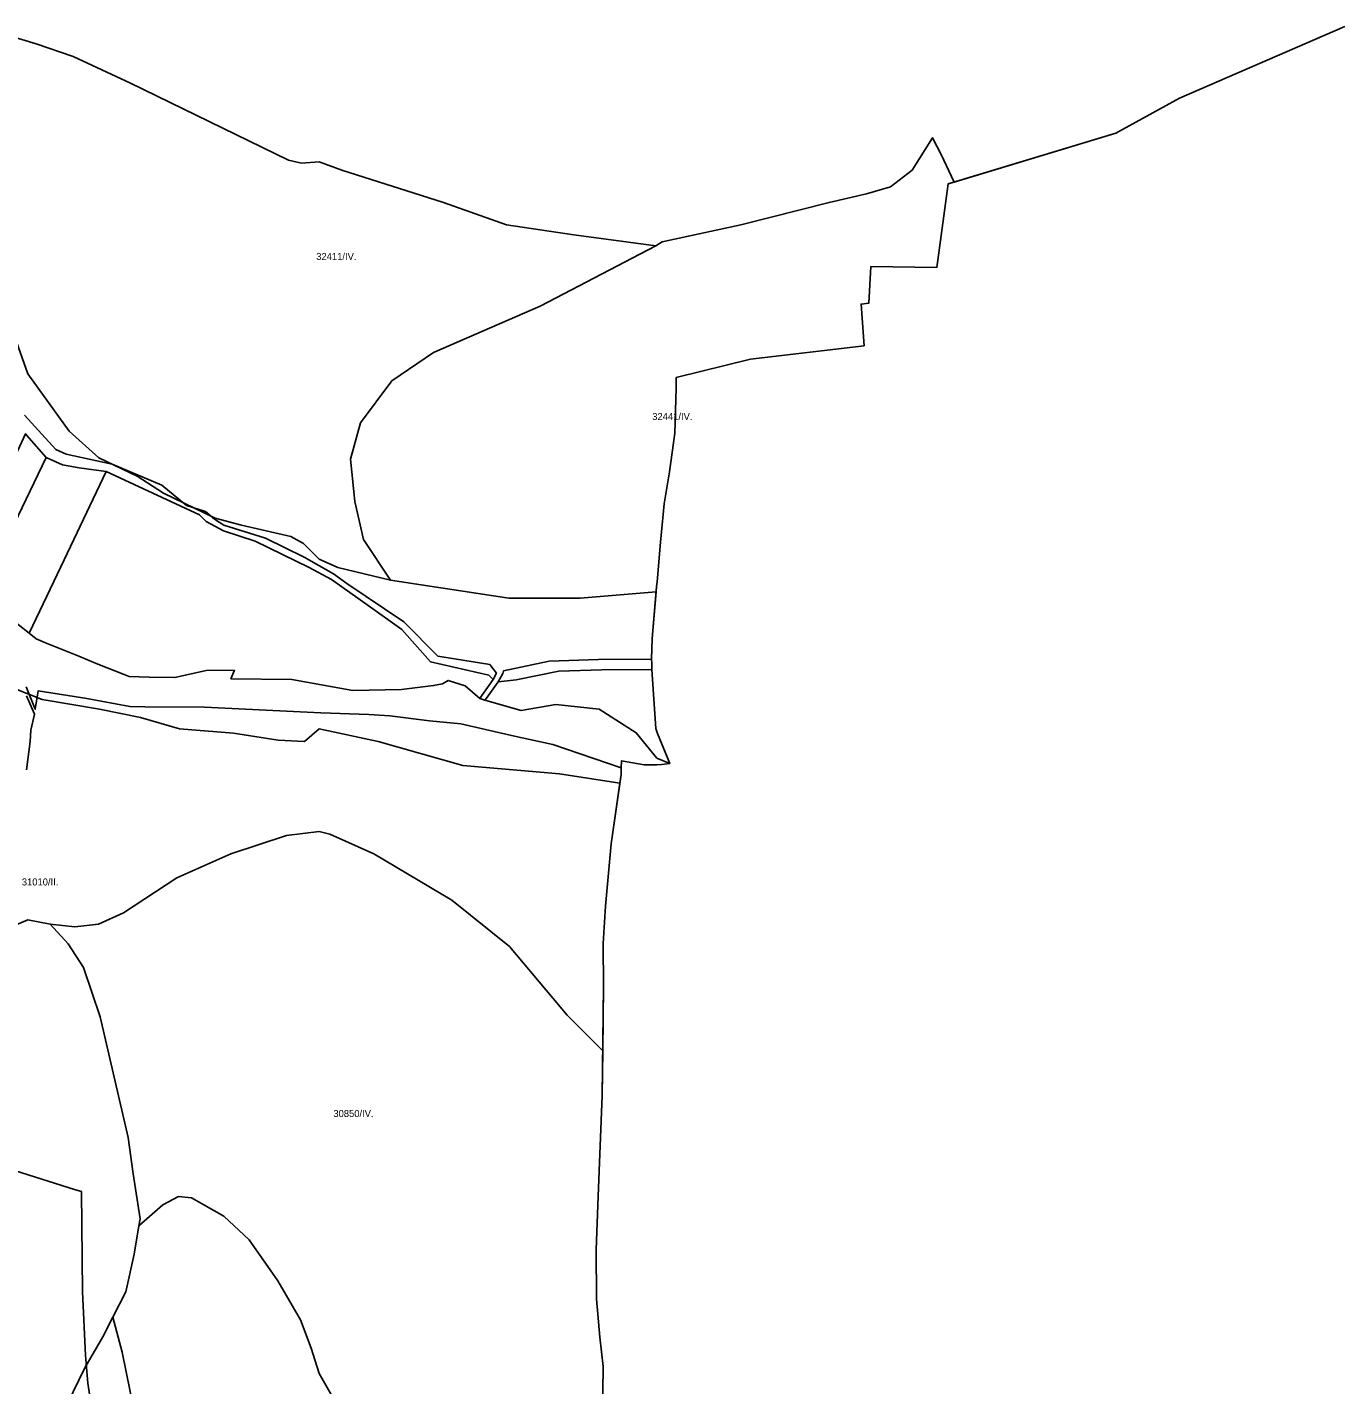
# Model space of a CAD drawing. Extents: x -532083 to -529270, y -1180561 to -1176456.
# Drawn here: x -530208 to -529270, y -1178980 to -1178013 of the extents above; entities that cross this region are included whole.
import ezdxf

# ---------------------------------------------------------------- set-up
doc = ezdxf.new("R2010")
doc.units = 0
for name, color, linetype in [('95560013', 7, 'Continuous'), ('95610013', 7, 'Continuous'), ('95660013', 7, 'Continuous')]:
    doc.layers.add(name, color=color, linetype=linetype)

msp = doc.modelspace()

# ---------------------------------------------------------------- linework, layer by layer
at = {"layer": '95560013'}
for points in [[(-529269.7473, -1178012.83245), (-529387.4623, -1178063.76645), (-529432.6943, -1178088.77845), (-529552.1533, -1178124.84145), (-529560.0893, -1178184.37345), (-529607.1593, -1178183.72045), (-529608.6783, -1178209.83045), (-529614.1003, -1178210.48245), (-529611.9313, -1178240.07345), (-529692.7363, -1178249.55845), (-529745.8233, -1178262.77245), (-529745.8233, -1178270.26645), (-529746.6933, -1178302.34745), (-529750.5573, -1178329.90645), (-529754.2063, -1178352.72945), (-529756.9963, -1178380.07345), (-529759.3563, -1178408.33445), (-529759.7813, -1178411.60245), (-529762.7563, -1178448.69245), (-529763.2213, -1178463.39145), (-529800.9413, -1178463.50145), (-529836.1633, -1178464.65645), (-529868.6233, -1178471.58345), (-529869.0833, -1178473.66245), (-529872.5363, -1178479.43545), (-529880.8803, -1178491.07145), (-529881.9753, -1178492.59745), (-529885.5633, -1178491.34245), (-529884.0523, -1178489.20245), (-529876.0863, -1178477.92145), (-529873.6873, -1178473.20045), (-529878.5223, -1178467.19645), (-529915.3553, -1178461.19245), (-529939.6333, -1178436.85445), (-529980.2683, -1178409.34745), (-529989.7423, -1178402.59545), (-530010.6833, -1178390.59245), (-530038.1053, -1178377.08845), (-530067.7723, -1178367.83645), (-530074.5033, -1178363.58545), (-530080.7353, -1178358.08345), (-530094.3023, -1178353.86845), (-530111.8443, -1178339.44545), (-530147.2153, -1178324.44645), (-530179.9993, -1178317.23445), (-530187.4763, -1178314.06145), (-530209.6193, -1178289.54245)], [(-530208.4253, -1178483.00245), (-530202.0793, -1178499.00245), (-530199.8863, -1178485.79845), (-530165.3853, -1178491.40045), (-530134.6733, -1178497.00145), (-530123.9043, -1178497.20145), (-530081.6263, -1178497.60145), (-529998.8033, -1178501.45245), (-529964.4903, -1178502.82845), (-529949.6213, -1178503.74645), (-529921.4843, -1178507.18845), (-529898.9593, -1178509.44445), (-529860.8673, -1178518.07345), (-529833.6293, -1178524.03145), (-529785.0073, -1178540.72445), (-529785.0073, -1178545.59145), (-529792.0203, -1178594.94745), (-529795.9993, -1178639.36845), (-529797.7293, -1178665.74345), (-529797.4373, -1178696.58345), (-529798.4343, -1178774.21245), (-529801.2823, -1178845.71245), (-529802.7693, -1178884.07845), (-529802.5573, -1178918.82145), (-529800.2193, -1178946.31745), (-529797.8273, -1178967.16945), (-529798.1793, -1179002.39145)], [(-530208.2113, -1178542.10845), (-530205.6693, -1178522.00845), (-530205.0713, -1178514.00645), (-530202.6783, -1178502.60345), (-530208.1813, -1178489.37645)], [(-530154.8043, -1179042.84745), (-530164.6633, -1178979.01145), (-530166.2283, -1178959.12945), (-530168.3143, -1178913.87145), (-530169.1723, -1178842.43145), (-530173.3683, -1178841.37945), (-530216.8993, -1178827.43745)]]:
    msp.add_lwpolyline(points, dxfattribs=at)
for points in [[(-530243.0333, -1178421.17245), (-530259.4933, -1178411.81445), (-530209.0493, -1178302.79245), (-530206.2503, -1178306.00145), (-530194.2883, -1178319.80045)], [(-530206.4423, -1178444.85245), (-530221.9553, -1178432.50545), (-530243.0333, -1178421.17245), (-530194.2883, -1178319.80045), (-530182.6253, -1178324.89945), (-530170.6633, -1178326.99945), (-530151.5243, -1178329.69945), (-530183.8213, -1178397.49245)], [(-530138.6543, -1178474.28345), (-530157.5403, -1178467.01045), (-530171.0303, -1178461.25945), (-530194.6383, -1178451.61845), (-530201.3833, -1178448.91245), (-530206.4423, -1178444.85245), (-530183.8213, -1178397.49245), (-530151.5243, -1178329.69945), (-530085.1353, -1178360.59545), (-530080.3503, -1178365.39545), (-530067.9153, -1178372.01045), (-530045.4653, -1178379.25845), (-530007.0153, -1178398.15445), (-529991.0163, -1178406.69645), (-529964.9523, -1178425.07445), (-529940.9533, -1178442.15845), (-529920.5673, -1178465.19545), (-529879.1523, -1178474.84645), (-529876.0863, -1178477.92145), (-529884.0523, -1178489.20245), (-529885.5633, -1178491.34245), (-529895.8773, -1178482.39545), (-529908.1413, -1178478.48045), (-529912.0443, -1178480.99745), (-529918.4553, -1178482.11545), (-529941.3123, -1178484.91145), (-529975.8773, -1178485.75045), (-530019.3613, -1178477.92145), (-530062.7113, -1178477.27545), (-530060.2353, -1178471.20545), (-530080.3163, -1178471.48145), (-530102.5973, -1178476.44745), (-530121.0273, -1178476.17145), (-530135.0563, -1178475.62045)], [(-529856.1913, -1178499.98645), (-529881.9753, -1178492.59745), (-529880.8803, -1178491.07145), (-529872.5363, -1178479.43545), (-529859.6453, -1178478.04945), (-529829.2573, -1178471.81445), (-529798.6393, -1178470.89145), (-529763.1033, -1178470.60645), (-529760.1553, -1178512.82845), (-529759.0093, -1178516.19945), (-529750.3513, -1178537.74545), (-529759.5033, -1178533.93145), (-529774.2373, -1178515.68945), (-529800.4813, -1178499.06345), (-529831.3293, -1178495.59945)]]:
    msp.add_lwpolyline(points, close=True, dxfattribs=at)
at = {"layer": '95610013'}
msp.add_lwpolyline([(-530235.6433, -1178918.08545), (-530233.9753, -1178858.53445), (-530233.1583, -1178825.59545), (-530216.8993, -1178827.43745), (-530173.3683, -1178841.37945), (-530169.1723, -1178842.43145), (-530168.3143, -1178913.87145), (-530166.2283, -1178959.12945), (-530164.6633, -1178979.01145), (-530154.8043, -1179042.84745), (-530158.8983, -1179045.58545), (-530194.1503, -1179068.40045), (-530226.9003, -1179091.21545), (-530232.5843, -1179067.17745), (-530237.3683, -1179045.20245), (-530239.6343, -1179024.74345), (-530237.5493, -1178966.09445)], close=True, dxfattribs=at)
at = {"layer": '95660013'}
for points in [[(-529269.7473, -1178012.83245), (-529387.4623, -1178063.76645), (-529432.6943, -1178088.77845), (-529547.9643, -1178123.57645), (-529557.1253, -1178104.00045), (-529563.3123, -1178092.00045), (-529577.8753, -1178115.00045), (-529593.1873, -1178127.00045), (-529610.3753, -1178132.00045), (-529636.8753, -1178138.00045), (-529699.8123, -1178154.00045), (-529755.6873, -1178166.00045), (-529760.1253, -1178169.00045), (-529818.6253, -1178161.00045), (-529866.6253, -1178154.00045), (-529911.3753, -1178138.00045), (-529983.8753, -1178115.00045), (-530000.0003, -1178109.00045), (-530012.3753, -1178110.00045), (-530021.8123, -1178108.00045), (-530134.1253, -1178053.00045), (-530175.0003, -1178034.00045), (-530201.3753, -1178025.00045), (-530221.8123, -1178019.00045)], [(-530221.8123, -1178019.00045), (-530201.3753, -1178025.00045), (-530175.0003, -1178034.00045), (-530134.1253, -1178053.00045), (-530021.8123, -1178108.00045), (-530012.3753, -1178110.00045), (-530000.0003, -1178109.00045), (-529983.8753, -1178115.00045), (-529911.3753, -1178138.00045), (-529866.6253, -1178154.00045), (-529818.6253, -1178161.00045), (-529760.1253, -1178169.00045), (-529842.5003, -1178212.00045), (-529918.6253, -1178245.00045), (-529948.1253, -1178265.00045), (-529970.3753, -1178295.00045), (-529977.6253, -1178321.00045), (-529974.5003, -1178351.00045), (-529968.3753, -1178378.00045), (-529949.1253, -1178407.00045), (-529986.6873, -1178398.00045), (-530000.0003, -1178392.00045), (-530011.1253, -1178381.00045), (-530020.1253, -1178376.00045), (-530055.1253, -1178368.00045), (-530073.8753, -1178363.00045), (-530110.6253, -1178345.00045), (-530129.3753, -1178333.00045), (-530156.8123, -1178320.00045), (-530178.0003, -1178301.00045), (-530207.3753, -1178260.00045), (-530218.0003, -1178230.00045)], [(-530218.0003, -1178230.00045), (-530207.3753, -1178260.00045), (-530178.0003, -1178301.00045), (-530156.8123, -1178320.00045), (-530129.3753, -1178333.00045), (-530110.6253, -1178345.00045), (-530073.8753, -1178363.00045), (-530055.1253, -1178368.00045), (-530020.1253, -1178376.00045), (-530011.1253, -1178381.00045), (-530000.0003, -1178392.00045), (-529986.6873, -1178398.00045), (-529949.1253, -1178407.00045), (-529864.8123, -1178420.00045), (-529814.1253, -1178420.00045), (-529760.0863, -1178415.40945), (-529762.7563, -1178448.69245), (-529763.2213, -1178463.39145), (-529763.1033, -1178466.11245), (-529763.1033, -1178470.60645), (-529760.1553, -1178512.82845), (-529759.0093, -1178516.19945), (-529750.3513, -1178537.74545), (-529756.2703, -1178538.40545), (-529759.5573, -1178538.51545), (-529768.4353, -1178538.51545), (-529784.6553, -1178535.65745), (-529785.0073, -1178540.72445), (-529785.0073, -1178545.59145), (-529785.8703, -1178551.66345), (-529828.8123, -1178545.00045), (-529897.6253, -1178539.00045), (-529957.8753, -1178522.00045), (-530000.0003, -1178513.00045), (-530010.3123, -1178522.00045), (-530029.0003, -1178521.00045), (-530060.8753, -1178516.00045), (-530099.3123, -1178513.00045), (-530127.0003, -1178505.00045), (-530156.3753, -1178499.00045), (-530197.1873, -1178492.00045), (-530220.0003, -1178483.00045)], [(-530220.0003, -1178483.00045), (-530197.1873, -1178492.00045), (-530156.3753, -1178499.00045), (-530127.0003, -1178505.00045), (-530099.3123, -1178513.00045), (-530060.8753, -1178516.00045), (-530029.0003, -1178521.00045), (-530010.3123, -1178522.00045), (-530000.0003, -1178513.00045), (-529957.8753, -1178522.00045), (-529897.6253, -1178539.00045), (-529828.8123, -1178545.00045), (-529785.8703, -1178551.66345), (-529792.0203, -1178594.94745), (-529795.9993, -1178639.36845), (-529797.7293, -1178665.74345), (-529797.4373, -1178696.58345), (-529798.0243, -1178742.26245), (-529823.3753, -1178717.00045), (-529864.3753, -1178668.00045), (-529905.3753, -1178635.00045), (-529961.0003, -1178602.00045), (-529992.3753, -1178588.00045), (-530000.0003, -1178586.00045), (-530023.1253, -1178589.00045), (-530062.8753, -1178602.00045), (-530101.1253, -1178619.00045), (-530139.1873, -1178644.00045), (-530157.0003, -1178652.00045), (-530173.8753, -1178654.00045), (-530191.3123, -1178652.00045), (-530207.3753, -1178649.00045), (-530221.0003, -1178655.00045)], [(-529970.1873, -1179024.00045), (-530000.0003, -1178972.00045), (-530005.6253, -1178954.00045), (-530013.3123, -1178934.00045), (-530029.3753, -1178906.00045), (-530049.8123, -1178877.00045), (-530067.6873, -1178860.00045), (-530090.6873, -1178847.00045), (-530100.1253, -1178846.00045), (-530111.1253, -1178852.00045), (-530128.1873, -1178867.00045), (-530127.3123, -1178862.00045), (-530132.3753, -1178830.00045), (-530135.8123, -1178804.00045), (-530155.8123, -1178718.00045), (-530167.6253, -1178683.00045), (-530178.6253, -1178666.00045), (-530191.3123, -1178652.00045), (-530173.8753, -1178654.00045), (-530157.0003, -1178652.00045), (-530139.1873, -1178644.00045), (-530101.1253, -1178619.00045), (-530062.8753, -1178602.00045), (-530023.1253, -1178589.00045), (-530000.0003, -1178586.00045), (-529992.3753, -1178588.00045), (-529961.0003, -1178602.00045), (-529905.3753, -1178635.00045), (-529864.3753, -1178668.00045), (-529823.3753, -1178717.00045), (-529798.0243, -1178742.26245), (-529798.4343, -1178774.21245), (-529801.2823, -1178845.71245), (-529802.7693, -1178884.07845), (-529802.5573, -1178918.82145), (-529800.2193, -1178946.31745), (-529797.8273, -1178967.16945), (-529798.1793, -1179002.39145)], [(-530221.0003, -1178655.00045), (-530207.3753, -1178649.00045), (-530191.3123, -1178652.00045), (-530178.6253, -1178666.00045), (-530167.6253, -1178683.00045), (-530155.8123, -1178718.00045), (-530135.8123, -1178804.00045), (-530132.3753, -1178830.00045), (-530127.3123, -1178862.00045), (-530128.1873, -1178867.00045), (-530131.6253, -1178887.00045), (-530137.5003, -1178914.00045), (-530146.8123, -1178932.00045), (-530154.0003, -1178946.00045), (-530166.8123, -1178968.00045), (-530179.3753, -1178994.00045)], [(-530131.6253, -1178999.00045), (-530140.1253, -1178957.00045), (-530146.8123, -1178932.00045), (-530137.5003, -1178914.00045), (-530131.6253, -1178887.00045), (-530128.1873, -1178867.00045), (-530111.1253, -1178852.00045), (-530100.1253, -1178846.00045), (-530090.6873, -1178847.00045), (-530067.6873, -1178860.00045), (-530049.8123, -1178877.00045), (-530029.3753, -1178906.00045), (-530013.3123, -1178934.00045), (-530005.6253, -1178954.00045), (-530000.0003, -1178972.00045), (-529970.1873, -1179024.00045)], [(-530179.3753, -1178994.00045), (-530166.8123, -1178968.00045), (-530154.0003, -1178946.00045), (-530146.8123, -1178932.00045), (-530140.1253, -1178957.00045), (-530131.6253, -1178999.00045)]]:
    msp.add_lwpolyline(points, dxfattribs=at)
msp.add_lwpolyline([(-529949.1253, -1178407.00045), (-529968.3753, -1178378.00045), (-529974.5003, -1178351.00045), (-529977.6253, -1178321.00045), (-529970.3753, -1178295.00045), (-529948.1253, -1178265.00045), (-529918.6253, -1178245.00045), (-529842.5003, -1178212.00045), (-529760.1253, -1178169.00045), (-529755.6873, -1178166.00045), (-529699.8123, -1178154.00045), (-529636.8753, -1178138.00045), (-529610.3753, -1178132.00045), (-529593.1873, -1178127.00045), (-529577.8753, -1178115.00045), (-529563.3123, -1178092.00045), (-529557.1253, -1178104.00045), (-529547.9643, -1178123.57645), (-529552.1533, -1178124.84145), (-529560.0893, -1178184.37345), (-529607.1593, -1178183.72045), (-529608.6783, -1178209.83045), (-529614.1003, -1178210.48245), (-529611.9313, -1178240.07345), (-529692.7363, -1178249.55845), (-529745.8233, -1178262.77245), (-529745.8233, -1178270.26645), (-529746.6933, -1178302.34745), (-529750.5573, -1178329.90645), (-529754.2063, -1178352.72945), (-529756.9963, -1178380.07345), (-529759.3563, -1178408.33445), (-529759.7813, -1178411.60245), (-529760.0863, -1178415.40945), (-529814.1253, -1178420.00045), (-529864.8123, -1178420.00045)], close=True, dxfattribs=at)

# ---------------------------------------------------------------- texts
for s, rotation, p in [('32411/IV.', 359.99999997, (-530001.98788, -1178179.00045)), ('32441/IV.', 359.99999998, (-529762.7948, -1178293.01675)), ('31010/II.', 0, (-530211.5956, -1178624.50045)), ('30850/IV.', 359.99999997, (-529989.8073, -1178789.46273))]:
    msp.add_text(s, height=5, rotation=rotation, dxfattribs=at).set_placement(p)

doc.saveas('drawing.dxf')
